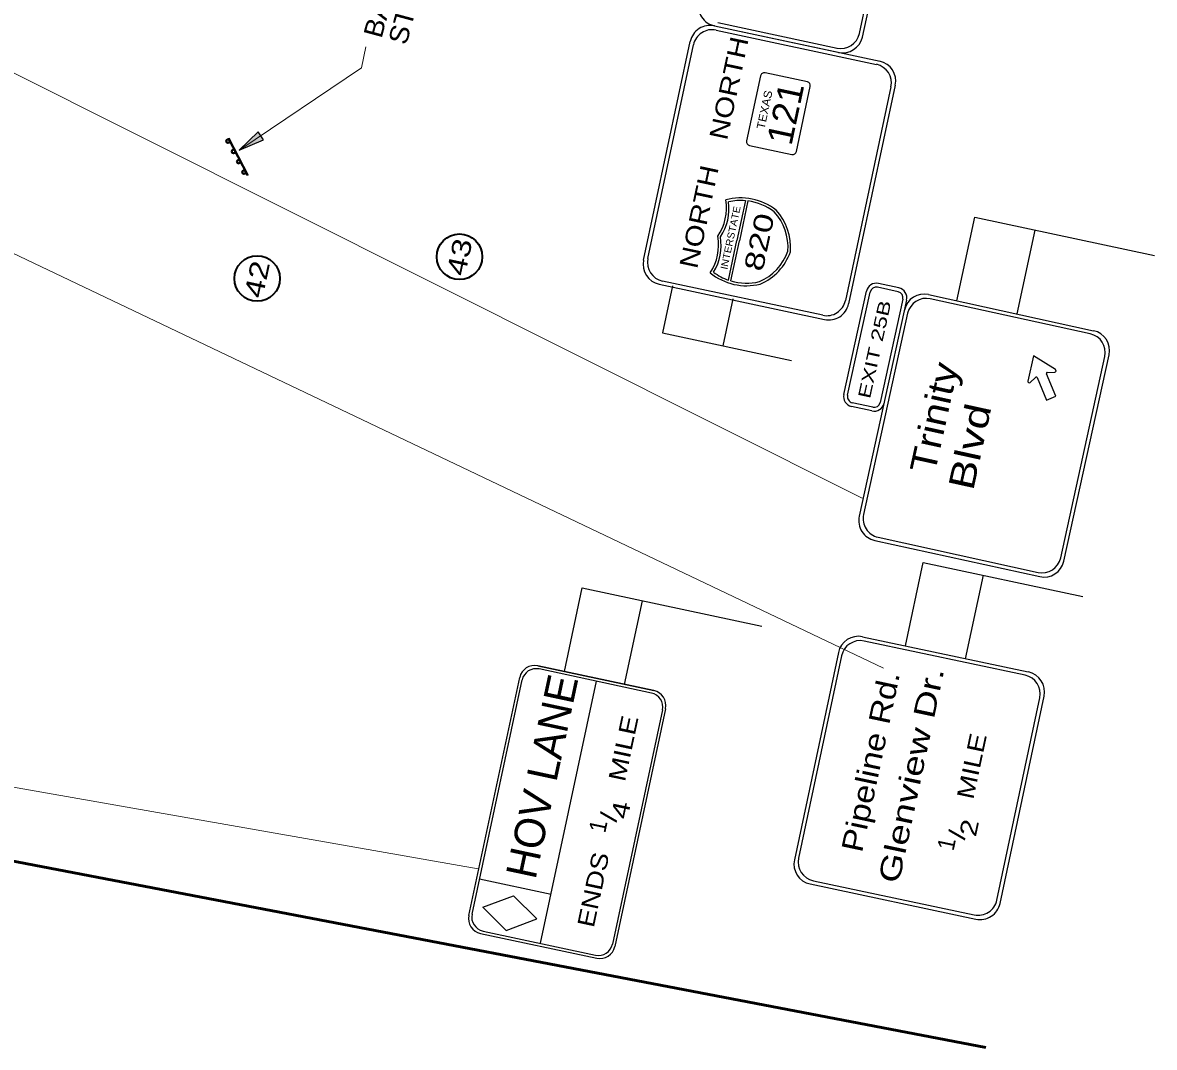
# Model space of a CAD drawing. Extents: x 2363411 to 2369702, y 6977197 to 6988655.
# Drawn here: x 2364967 to 2365803, y 6978864 to 6979621 of the extents above; entities that cross this region are included whole.
import ezdxf
from ezdxf.enums import TextEntityAlignment as Align

# ---------------------------------------------------------------- set-up
doc = ezdxf.new("R2010")
doc.units = 0
doc.header["$LTSCALE"] = 5.6
for name, color, linetype, lineweight in [('1', 7, 'Continuous', 25), ('17', 7, 'Continuous', 35), ('48', 7, 'Continuous', 25), ('63', 7, 'Continuous', 13)]:
    doc.layers.add(name, color=color, linetype=linetype, lineweight=lineweight)

msp = doc.modelspace()

# ---------------------------------------------------------------- hatches: boundary and pattern name
at = {"layer": '1'}
msp.add_hatch(color=256, dxfattribs=at).paths.add_polyline_path([(2365127.003, 6979526.823), (2365145.017, 6979534.373), (2365141.062, 6979540.391)])

# ---------------------------------------------------------------- linework, layer by layer
for p, q in [((2365585.042, 6979613.077), (2365622.798, 6979789.762)), ((2365587.346, 6979610.351), (2365625.84, 6979790.529)), ((2365477.944, 6979618.641), (2365600.338, 6979592.485)), ((2365477.944, 6979618.641), (2365569.266, 6979599.126)), ((2365479.197, 6979615.508), (2365597.544, 6979590.217)), ((2365480.38, 6979621.011), (2365568.681, 6979602.141)), ((2365425.642, 6979445.631), (2365460.153, 6979607.112)), ((2365428.783, 6979446.876), (2365462.514, 6979604.689)), ((2365512.046, 6979581.787), (2365501.752, 6979533.63)), ((2365546.615, 6979577.266), (2365515.382, 6979583.946)), ((2365538.486, 6979525.78), (2365548.781, 6979573.931)), ((2365608.362, 6979573.533), (2365574.64, 6979415.713)), ((2365611.497, 6979574.779), (2365576.994, 6979413.291)), ((2365503.918, 6979530.294), (2365535.15, 6979523.614)), ((2365500.851, 6979489.544), (2365494.586, 6979460.207)), ((2365502.743, 6979489.334), (2365496.434, 6979459.814)), ((2365657.088, 6979415.559), (2365670.27, 6979477.257)), ((2365670.27, 6979477.257), (2365802.852, 6979448.929)), ((2365701.555, 6979405.885), (2365714.774, 6979467.747)), ((2365488.319, 6979430.87), (2365494.586, 6979460.207)), ((2365490.128, 6979430.271), (2365496.434, 6979459.814)), ((2365557.957, 6979404.894), (2365439.596, 6979430.185)), ((2365437.188, 6979427.833), (2365559.204, 6979401.752)), ((2365447.004, 6979426.621), (2365439.574, 6979391.849)), ((2365573.474, 6979346.473), (2365590.181, 6979422.63)), ((2365576.227, 6979345.872), (2365592.927, 6979422.027)), ((2365613.582, 6979422.295), (2365598.509, 6979425.605)), ((2365614.187, 6979425.047), (2365599.113, 6979428.349)), ((2365491.506, 6979417.109), (2365484.078, 6979382.339)), ((2365619.911, 6979416.109), (2365584.902, 6979256.474)), ((2365617.158, 6979416.72), (2365600.452, 6979340.554)), ((2365636.168, 6979420.225), (2365757.98, 6979393.51)), ((2365755.544, 6979391.161), (2365637.397, 6979417.069)), ((2365620.64, 6979406.355), (2365588.042, 6979257.703)), ((2365439.574, 6979391.849), (2365534.826, 6979371.497)), ((2365733.669, 6979225.761), (2365766.268, 6979374.412)), ((2365736.019, 6979223.327), (2365769.423, 6979375.649)), ((2365723.805, 6979362.67), (2365729.344, 6979362.909)), ((2365711.072, 6979355.312), (2365715.124, 6979359.031)), ((2365716.226, 6979358.834), (2365716.236, 6979358.843)), ((2365594.274, 6979334.241), (2365579.2, 6979337.543)), ((2365594.877, 6979336.985), (2365579.804, 6979340.287)), ((2365596.338, 6979238.607), (2365718.156, 6979211.89)), ((2365598.773, 6979240.947), (2365716.92, 6979215.037)), ((2365663.497, 6979151.078), (2365676.716, 6979212.94)), ((2365367.213, 6979141.827), (2365380.395, 6979203.525)), ((2365380.395, 6979203.525), (2365512.977, 6979175.197)), ((2365411.68, 6979132.153), (2365424.899, 6979194.015)), ((2365587.337, 6979167.479), (2365709.766, 6979141.493)), ((2365707.341, 6979139.106), (2365588.603, 6979164.317)), ((2365569.503, 6979155.891), (2365537.01, 6979002.791)), ((2365571.861, 6979153.449), (2365540.142, 6979004.048)), ((2365686.52, 6978972.973), (2365718.231, 6979122.38)), ((2365688.876, 6978970.554), (2365721.371, 6979123.631)), ((2365551.032, 6978987.322), (2365669.77, 6978962.112)), ((2365548.584, 6978984.942), (2365671.02, 6978958.949))]:
    msp.add_line(p, q, dxfattribs=at)
at = {"layer": '1', "lineweight": 13}
for p, q in [((2364675.941, 6979726.259), (2365587.007, 6979269.736)), ((2364811.897, 6979521.098), (2365602.925, 6979144.273)), ((2364602.343, 6979119.226), (2365303.581, 6978996.095))]:
    msp.add_line(p, q, dxfattribs=at)
at = {"layer": '1', "lineweight": 53}
msp.add_line((2365678.349, 6978864.266), (2363870.127, 6979210.247), dxfattribs=at)
at = {"layer": '1'}
msp.add_lwpolyline([(2365127.003, 6979526.823), (2365145.017, 6979534.373), (2365141.062, 6979540.391)], close=True, dxfattribs=at)
for points in [[(2365729.751, 6979364.808), (2365713.53, 6979375.003), (2365709.412, 6979356.31)], [(2365716.236, 6979358.843), (2365723.096, 6979342.283), (2365726.585, 6979343.749), (2365730.155, 6979345.249), (2365723.166, 6979361.704)], [(2365619.03, 6979160.752), (2365632.212, 6979222.45), (2365749.932, 6979197.298)]]:
    msp.add_lwpolyline(points, dxfattribs=at)
for centre, radius, start, end in [((2365481.093, 6979633.364), 15.049, 167.93925, 257.93925), ((2365474.819, 6979603.979), 15.001, 77.94013, 167.94013), ((2365476.261, 6979601.754), 14.063, 77.94013, 167.94013), ((2365571.246, 6979616.025), 14.108, 257.93925, 347.93925), ((2365572.693, 6979613.793), 15.049, 257.93925, 346.76968), ((2365594.608, 6979576.469), 14.063, 347.94013, 77.94013), ((2365596.834, 6979577.911), 15.001, 347.94013, 77.94013), ((2365514.797, 6979581.194), 2.813, 77.93906, 167.93906), ((2365546.024, 6979574.522), 2.813, 347.93906, 77.93906), ((2365504.508, 6979533.041), 2.813, 167.93906, 257.93906), ((2365535.736, 6979526.369), 2.813, 257.93906, 347.93906), ((2365450.88, 6979483.808), 35.984, 325.11963, 9.96995), ((2365450.88, 6979483.808), 37.874, 326.31755, 7.31439), ((2365497.536, 6979449.611), 41.954, 51.80243, 105.50481), ((2365497.536, 6979449.611), 40.064, 85.24888, 103.11363), ((2365497.536, 6979449.611), 40.064, 52.01897, 82.53095), ((2365493.545, 6979455.01), 38.808, 355.77729, 42.42367), ((2365493.545, 6979455.01), 40.698, 355.41114, 42.64704), ((2365445.048, 6979456.513), 35.984, 325.90855, 10.75886), ((2365445.048, 6979456.513), 37.874, 328.56411, 9.56095), ((2365440.313, 6979442.495), 15.001, 167.94013, 257.94013), ((2365442.538, 6979443.937), 14.063, 167.94013, 257.94013), ((2365495.756, 6979465.361), 38.808, 293.45483, 340.10121), ((2365495.756, 6979465.361), 40.698, 293.23145, 340.46735), ((2365501.606, 6979468.657), 41.954, 230.37369, 284.07606), ((2365501.606, 6979468.657), 40.064, 232.76486, 250.62962), ((2365501.606, 6979468.657), 40.064, 253.34754, 283.85953), ((2365597.508, 6979421.033), 7.497, 77.63055, 167.63055), ((2365597.508, 6979421.033), 4.686, 77.63055, 167.63055), ((2365612.594, 6979417.725), 4.686, 347.63055, 77.63055), ((2365612.594, 6979417.725), 7.497, 347.63055, 77.63055), ((2365632.957, 6979405.584), 14.995, 77.63055, 167.63055), ((2365560.886, 6979418.653), 14.063, 257.94013, 347.94013), ((2365562.328, 6979416.427), 15.001, 257.94013, 347.94013), ((2365634.387, 6979403.351), 14.057, 77.63055, 167.63055), ((2365752.548, 6979377.438), 14.057, 347.63055, 77.63055), ((2365754.78, 6979378.867), 14.995, 347.63055, 77.63055), ((2365723.824, 6979362.002), 0.675, 92.64744, 202.63055), ((2365729.266, 6979363.935), 1.012, 272.51091, 57.89205), ((2365710.399, 6979356.07), 1.012, 167.36904, 312.75018), ((2365715.603, 6979358.574), 0.675, 22.63055, 132.61365), ((2365580.805, 6979344.871), 7.497, 167.63055, 257.63055), ((2365580.805, 6979344.871), 4.686, 167.63055, 257.63055), ((2365595.891, 6979341.563), 7.497, 257.63055, 347.63055), ((2365595.891, 6979341.563), 4.686, 257.63055, 347.63055), ((2365599.552, 6979253.259), 14.995, 167.63055, 257.63055), ((2365601.784, 6979254.688), 14.057, 167.63055, 257.63055), ((2365719.946, 6979228.775), 14.057, 257.63055, 347.63055), ((2365721.375, 6979226.542), 14.995, 257.63055, 347.63055), ((2365584.22, 6979152.764), 15.049, 78.01448, 168.01448), ((2365585.669, 6979150.533), 14.108, 78.01448, 168.01447), ((2365704.428, 6979125.322), 14.108, 348.01448, 78.01448), ((2365706.658, 6979126.771), 15.049, 348.01447, 78.01447), ((2365551.719, 6978999.669), 15.049, 168.01448, 258.01448), ((2365553.95, 6979001.119), 14.108, 168.01447, 258.01447), ((2365672.708, 6978975.907), 14.108, 258.01447, 348.01447), ((2365674.158, 6978973.677), 15.049, 258.01447, 348.01447)]:
    msp.add_arc(centre, radius, start, end, dxfattribs=at)
at = {"layer": '17'}
for centre in [(2365289.699, 6979448.112), (2365140.286, 6979432.03)]:
    msp.add_circle(centre, 16.828, dxfattribs=at)
at = {"layer": '48'}
for p, q in [((2365347.504, 6979146.039), (2365433.251, 6979127.714)), ((2365433.251, 6979127.714), (2365347.504, 6979146.039)), ((2365296.625, 6978961.758), (2365334.158, 6979137.392)), ((2365431.435, 6979125.945), (2365348.434, 6979143.69)), ((2365298.97, 6978962.694), (2365335.903, 6979135.575)), ((2365349.521, 6978941.104), (2365390.864, 6979134.624)), ((2365439.543, 6979113.426), (2365402.609, 6978940.547)), ((2365441.9, 6979114.366), (2365404.384, 6978938.728)), ((2365304.537, 6978988.758), (2365357.295, 6978977.485)), ((2365306.855, 6978967.703), (2365329.568, 6978976.273)), ((2365346.794, 6978959.17), (2365329.568, 6978976.273)), ((2365324.082, 6978950.6), (2365306.855, 6978967.703)), ((2365324.082, 6978950.6), (2365346.794, 6978959.17)), ((2365305.276, 6978948.405), (2365391.029, 6978930.078)), ((2365307.092, 6978950.174), (2365390.095, 6978932.435))]:
    msp.add_line(p, q, dxfattribs=at)
for centre, radius, start, end in [((2365345.157, 6979135.039), 11.251, 77.93633, 167.93633), ((2365346.239, 6979133.37), 10.548, 77.93633, 167.93633), ((2365429.231, 6979115.629), 10.548, 347.93633, 77.93633), ((2365430.9, 6979116.711), 11.251, 347.93633, 77.93633), ((2365307.627, 6978959.406), 11.251, 167.93575, 257.93575), ((2365309.296, 6978960.488), 10.548, 167.93575, 257.93575), ((2365392.3, 6978942.749), 10.548, 257.93575, 347.93575), ((2365393.381, 6978941.08), 11.251, 257.93575, 347.93575)]:
    msp.add_arc(centre, radius, start, end, dxfattribs=at)
at = {"layer": '63', "lineweight": 40}
msp.add_line((2365133.473, 6979508.108), (2365119.199, 6979535.673), dxfattribs=at)
at = {"layer": '63'}
msp.add_lwpolyline([(2365127.431, 6979526.989), (2365217.246, 6979587.561), (2365220.566, 6979603.099)], dxfattribs=at)
at = {"layer": '63', "lineweight": 40}
for centre in [(2365118.729, 6979533.495), (2365122.871, 6979525.891), (2365126.645, 6979518.365), (2365130.564, 6979510.618)]:
    msp.add_circle(centre, 1.355, dxfattribs=at)

# ---------------------------------------------------------------- texts
at = {"layer": '1'}
for s, height, rotation, width, p in [('BARRICADE ', 14, 74.944, 1.1, (2365232.095, 6979608.769)), ('STREET', 14, 74.944, 1.1, (2365250.443, 6979603.833)), ('121', 18.75, 77.939, 1.1, (2365534.776, 6979529.508)), ('TEXAS', 6, 77.939, 1.1, (2365514.88, 6979541.909)), ('INTERSTATE', 5.198, 77.939, 1.1, (2365487.438, 6979438.341)), ('820', 14.18, 77.939, 1.35, (2365513.507, 6979436.592))]:
    msp.add_text(s, height=height, rotation=rotation, dxfattribs=dict(at, width=width)).set_placement(p)
for s, height, rotation, width, p in [('NORTH', 13.5, 77.94, 1.2, (2365495.267, 6979571.228)), ('NORTH', 13.5, 77.94, 1.2, (2365473.198, 6979476.275)), ('EXIT 25B', 9.184, 77.631, 1.4, (2365600.708, 6979378.749)), ('Trinity', 18.9, 77.631, 1.2, (2365649.431, 6979327.349)), ('Blvd', 18.9, 77.631, 1.3, (2365675.81, 6979305.933)), ('Pipeline Rd.', 15.68, 78.014, 1.2, (2365600.984, 6979073.815)), ('Glenview Dr.', 15.68, 78.014, 1.35, (2365630.977, 6979063.804)), ('MILE', 12.54, 78.014, 1.25, (2365416.915, 6979083.783)), ('MILE', 12.54, 78.014, 1.25, (2365674.156, 6979070.656)), ('4', 12.54, 78.014, 1.35, (2365414.969, 6979038.242)), ('/', 12.54, 78.014, 1.3, (2365406.163, 6979033.112)), ('1', 12.54, 78.014, 0.95, (2365398.208, 6979026.37)), ('2', 12.54, 78.014, 1.3, (2365672.209, 6979025.115)), ('/', 12.54, 78.014, 1.3, (2365663.404, 6979019.985)), ('1', 12.54, 78.014, 0.95, (2365655.449, 6979013.243)), ('ENDS', 12.54, 78.014, 1.2, (2365394.619, 6978979.436))]:
    msp.add_text(s, height=height, rotation=rotation, dxfattribs=dict(at, width=width)).set_placement(p, align=Align.CENTER)
at = {"layer": '17', "width": 1.3}
for s, p in [('43', (2365296.506, 6979446.473)), ('42', (2365147.019, 6979430.044))]:
    msp.add_text(s, height=14, rotation=77.939, dxfattribs=at).set_placement(p, align=Align.CENTER)
at = {"layer": '48'}
msp.add_text('HOV LANE', height=22.5, rotation=77.935, dxfattribs=at).set_placement((2365361.67, 6979061.973), align=Align.CENTER)

doc.saveas('drawing.dxf')
